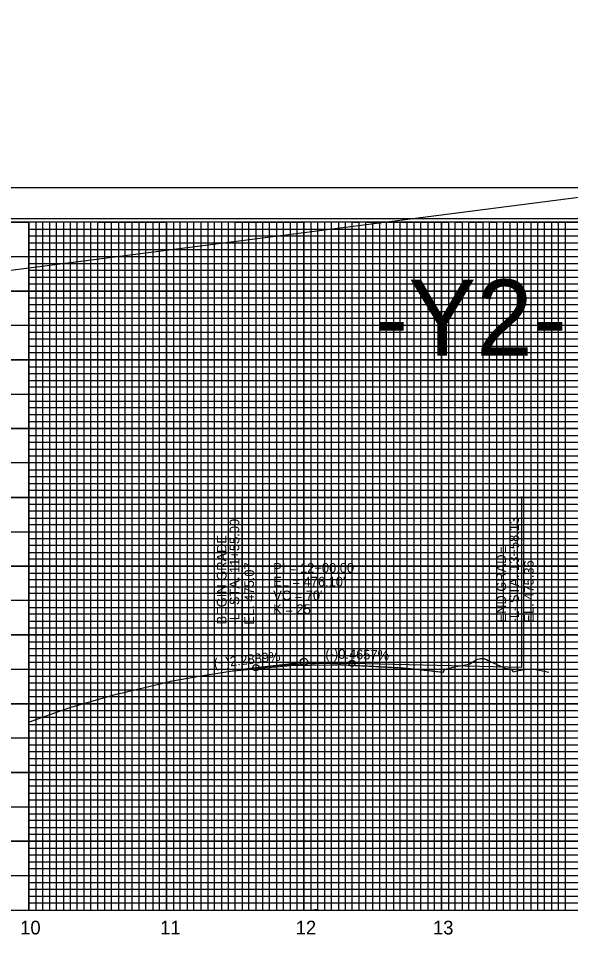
# Model space of a CAD drawing. Extents: x 571503 to 593215, y -77195 to -51828.
# Drawn here: x 586568 to 586970, y -53168 to -52498 of the extents above; entities that cross this region are included whole.
import ezdxf

# ---------------------------------------------------------------- set-up
doc = ezdxf.new("R2010")
doc.units = 0
for name, color, linetype in [('Default', 7, 'Continuous'), ('Exist Vertical Profile Ground Line', 7, 'Continuous'), ('Exist Vertical Profile Horizontal Axis Label Major', 7, 'Continuous'), ('Prop PFL Text', 7, 'Continuous'), ('Prop Vertical Profile Curve Label', 7, 'Continuous'), ('Prop Vertical Profile Grade', 7, 'Continuous'), ('Prop Vertical Profile Grade Label', 7, 'Continuous'), ('Prop VPI Label', 7, 'Continuous'), ('Sheet Clip Boundary CELL', 7, 'Continuous'), ('Sheet DOT Grid CELL', 7, 'Continuous'), ('Sheet Plot Border Inside CELL', 7, 'Continuous'), ('Sheet Plot Border Outside CELL', 7, 'Continuous'), ('Sheet Profile CELL', 7, 'Continuous'), ('Sheet Profile Grid Major CELL', 7, 'Continuous'), ('Sheet Profile Grid Middle CELL', 7, 'Continuous'), ('Sheet Profile Grid Minor CELL', 7, 'Continuous')]:
    doc.layers.add(name, color=color, linetype=linetype)

msp = doc.modelspace()

# ---------------------------------------------------------------- linework, layer by layer
at = {"layer": 'Default'}
msp.add_line((586525.93, -53146.12), (586575.93, -53146.12), dxfattribs=at)
at = {"layer": 'Exist Vertical Profile Ground Line'}
for points in [[(586878.41, -52970.95), (586878.53, -52970.95), (586879.2, -52970.94), (586879.66, -52970.83), (586880.92, -52970.53), (586882.18, -52970.22), (586883.43, -52969.9), (586884.69, -52969.58), (586885.94, -52969.26), (586887.2, -52968.93), (586887.9, -52968.74), (586888.46, -52968.66), (586889.71, -52968.48), (586890.97, -52968.29), (586892.23, -52968.1), (586893.48, -52967.9), (586894.74, -52967.7), (586895.99, -52967.5), (586896.12, -52967.48), (586897.25, -52966.75), (586898.51, -52965.94), (586899.76, -52965.11), (586901.02, -52964.28), (586901.4, -52964.02), (586902.28, -52963.83), (586903.53, -52963.54), (586904.37, -52963.34), (586904.79, -52963.31), (586906.04, -52963.2), (586906.68, -52963.14), (586907.3, -52963.43), (586908.56, -52964.03), (586909.81, -52964.62), (586911.07, -52965.21), (586912.33, -52965.8), (586913.58, -52966.38), (586921.58, -52970.06), (586926.71, -52970.98), (586928.18, -52972.84), (586932.26, -52971.92), (586937.85, -52971.04), (586942.73, -52970.78), (586953.96, -52973.11), (586954.06, -52973.13)], [(586575.93, -53009.48), (586576.18, -53009.4), (586576.18, -53009.4), (586607.14, -52998.5), (586607.29, -52998.45), (586608.38, -52998.1), (586635.32, -52990.4), (586639.22, -52989.26), (586646.02, -52987.64), (586648.78, -52987.02), (586678.39, -52979.89), (586678.74, -52979.81), (586696.99, -52976.55), (586699.56, -52976.17), (586724.04, -52972.33), (586724.63, -52972.27), (586755.51, -52969.4), (586756.19, -52969.34), (586765.89, -52968.43), (586765.91, -52968.43), (586795.49, -52967.85), (586796.19, -52967.84), (586796.75, -52967.83), (586798.01, -52967.8), (586798.12, -52967.8), (586799.26, -52967.78), (586800.52, -52967.76), (586801.77, -52967.73), (586802.47, -52967.72), (586803.03, -52967.74), (586803.71, -52967.77), (586804.29, -52967.8), (586805.54, -52967.86), (586806.8, -52967.92), (586808.06, -52967.98), (586809.31, -52968.04), (586810.57, -52968.1), (586811.82, -52968.16), (586813.08, -52968.22), (586814.34, -52968.28), (586815.59, -52968.35), (586816.85, -52968.41), (586818.11, -52968.47), (586819.36, -52968.54), (586820.62, -52968.61), (586821.87, -52968.67), (586823.13, -52968.74), (586824.39, -52968.81), (586825.64, -52968.87), (586826.9, -52968.94), (586828.16, -52969.01), (586829.41, -52969.08), (586830.39, -52969.14), (586830.67, -52969.15), (586831.92, -52969.22), (586833.18, -52969.28), (586834.44, -52969.35), (586835.69, -52969.41), (586836.95, -52969.48), (586838.21, -52969.54), (586839.46, -52969.61), (586840.7, -52969.68), (586840.72, -52969.68), (586841.97, -52969.75), (586843.23, -52969.83), (586844.49, -52969.9), (586845.74, -52969.97), (586847, -52970.05), (586848.26, -52970.12), (586849.51, -52970.2), (586850.59, -52970.27), (586850.77, -52970.29), (586852.03, -52970.42), (586853.28, -52970.56), (586854.54, -52970.7), (586855.79, -52970.83), (586857.05, -52970.97), (586858.31, -52971.11), (586859.56, -52971.25), (586860.82, -52971.39), (586862.08, -52971.53), (586863.33, -52971.67), (586864.59, -52971.81), (586864.78, -52971.83), (586865.84, -52971.95), (586867.1, -52972.08), (586868.36, -52972.22), (586869.19, -52972.31), (586869.61, -52972.36), (586870.87, -52972.51), (586872.13, -52972.66), (586872.56, -52972.71), (586873.38, -52972.78), (586874.64, -52972.88), (586875.89, -52972.99), (586876.26, -52973.02), (586877.15, -52973.07), (586877.39, -52973.08), (586877.89, -52971.77), (586878.19, -52970.94), (586878.41, -52970.95)]]:
    msp.add_lwpolyline(points, dxfattribs=at)
at = {"layer": 'Prop PFL Text'}
msp.add_line((571799.62, -54572.45), (593215.36, -51828.37), dxfattribs=at)
at = {"layer": 'Prop Vertical Profile Curve Label'}
for centre in [(586810.93, -52966.69), (586740.93, -52969.88)]:
    msp.add_circle(centre, 2.25, dxfattribs=at)
at = {"layer": 'Prop Vertical Profile Grade'}
for p, q in [((586730.93, -52971.02), (586740.93, -52969.88)), ((586810.93, -52966.69), (586934.25, -52969.56))]:
    msp.add_line(p, q, dxfattribs=at)
msp.add_spline([(586740.93, -52969.88), (586742.33, -52969.72), (586743.73, -52969.57), (586745.13, -52969.42), (586746.53, -52969.27), (586747.93, -52969.13), (586749.33, -52968.99), (586750.73, -52968.85), (586752.13, -52968.72), (586753.53, -52968.59), (586754.93, -52968.47), (586756.33, -52968.35), (586757.73, -52968.23), (586759.13, -52968.12), (586760.53, -52968.01), (586761.93, -52967.91), (586763.33, -52967.81), (586764.73, -52967.71), (586766.13, -52967.62), (586767.53, -52967.53), (586768.93, -52967.45), (586770.33, -52967.36), (586771.73, -52967.29), (586773.13, -52967.21), (586774.53, -52967.14), (586775.93, -52967.08), (586777.33, -52967.02), (586778.73, -52966.96), (586780.13, -52966.9), (586781.53, -52966.85), (586782.93, -52966.81), (586784.33, -52966.77), (586785.73, -52966.73), (586787.13, -52966.69), (586788.53, -52966.66), (586789.93, -52966.63), (586791.33, -52966.61), (586792.73, -52966.59), (586794.13, -52966.57), (586795.53, -52966.56), (586796.93, -52966.56), (586798.33, -52966.55), (586799.73, -52966.55), (586801.13, -52966.55), (586802.53, -52966.56), (586803.93, -52966.57), (586805.33, -52966.59), (586806.73, -52966.61), (586808.13, -52966.63), (586809.53, -52966.66), (586810.93, -52966.69)], degree=3, dxfattribs=at)
at = {"layer": 'Prop VPI Label'}
for p, q in [((586730.93, -52971.02), (586730.93, -52846.89)), ((586934.25, -52969.56), (586934.25, -52845.43)), ((586740.93, -52969.88), (586773.2, -52966.19)), ((586810.93, -52966.69), (586778.68, -52965.94))]:
    msp.add_line(p, q, dxfattribs=at)
msp.add_circle((586775.93, -52965.87), 2.75, dxfattribs=at)
at = {"layer": 'Sheet Clip Boundary CELL'}
msp.add_lwpolyline([(585975.93, -52646.12), (585975.93, -53146.12), (587375.93, -53146.12), (587375.93, -52783.67), (587225.88, -52783.67), (587225.88, -52646.12)], close=True, dxfattribs=at)
at = {"layer": 'Sheet DOT Grid CELL'}
for p, q in [((586575.93, -53146.12), (586575.93, -52646.12)), ((586575.93, -53146.12), (586575.93, -52646.12)), ((586625.93, -53146.12), (586625.93, -52646.12)), ((586625.93, -53146.12), (586625.93, -52646.12)), ((586675.93, -53146.12), (586675.93, -52646.12)), ((586675.93, -53146.12), (586675.93, -52646.12)), ((586725.93, -53146.12), (586725.93, -52646.12)), ((586725.93, -53146.12), (586725.93, -52646.12)), ((586775.93, -53146.12), (586775.93, -52646.12)), ((586775.93, -53146.12), (586775.93, -52646.12)), ((586825.93, -53146.12), (586825.93, -52646.12)), ((586825.93, -53146.12), (586825.93, -52646.12)), ((586875.93, -53146.12), (586875.93, -52646.12)), ((586875.93, -53146.12), (586875.93, -52646.12)), ((586925.93, -53146.12), (586925.93, -52646.12)), ((586925.93, -53146.12), (586925.93, -52646.12)), ((587225.88, -52696.12), (585925.93, -52696.12)), ((585925.93, -52746.12), (587225.88, -52746.12)), ((587225.88, -52746.12), (585925.93, -52746.12)), ((585925.93, -52796.12), (587425.93, -52796.12)), ((587425.93, -52796.12), (585925.93, -52796.12)), ((585925.93, -52846.12), (587425.93, -52846.12)), ((587425.93, -52846.12), (586575.93, -52846.12)), ((587425.93, -52896.12), (585925.93, -52896.12)), ((586575.93, -52896.12), (587425.93, -52896.12)), ((585925.93, -52946.12), (587425.93, -52946.12)), ((587425.93, -52946.12), (585925.93, -52946.12)), ((585925.93, -52996.12), (587425.93, -52996.12)), ((587425.93, -52996.12), (585925.93, -52996.12)), ((585925.93, -53046.12), (587425.93, -53046.12)), ((587425.93, -53046.12), (585925.93, -53046.12)), ((585925.93, -53096.12), (587425.93, -53096.12)), ((587425.93, -53096.12), (585925.93, -53096.12))]:
    msp.add_line(p, q, dxfattribs=at)
at = {"layer": 'Sheet Plot Border Inside CELL'}
msp.add_lwpolyline([(585771.93, -53698.67), (587438.43, -53698.67), (587438.43, -52643.57), (585771.93, -52643.57)], close=True, dxfattribs=at)
at = {"layer": 'Sheet Plot Border Outside CELL'}
msp.add_lwpolyline([(585758.93, -53721.12), (587442.93, -53721.12), (587442.93, -52621.12), (585758.93, -52621.12)], close=True, dxfattribs=at)
at = {"layer": 'Sheet Profile CELL'}
for p, q in [((587442.93, -52621.12), (585758.93, -52621.12)), ((585925.93, -53146.12), (587425.93, -53146.12))]:
    msp.add_line(p, q, dxfattribs=at)
msp.add_lwpolyline([(587425.93, -52646.12), (585925.93, -52646.12), (585925.93, -53696.12), (587425.93, -53696.12)], close=True, dxfattribs=at)
at = {"layer": 'Sheet Profile Grid Major CELL'}
for points in [[(586525.93, -52646.12), (586575.93, -52646.12), (586575.93, -53146.12), (586625.93, -53146.12), (586625.93, -52646.12), (586675.93, -52646.12), (586675.93, -53146.12), (586725.93, -53146.12), (586725.93, -52646.12), (586775.93, -52646.12), (586775.93, -53146.12), (586825.93, -53146.12), (586825.93, -52646.12), (586875.93, -52646.12), (586875.93, -53146.12), (586925.93, -53146.12), (586925.93, -52646.12), (586975.93, -52646.12)], [(585925.93, -52696.12), (587225.93, -52696.12)], [(587225.93, -52746.12), (585925.93, -52746.12), (585925.93, -52796.12), (587425.93, -52796.12)], [(587425.93, -52846.12), (585925.93, -52846.12), (585925.93, -52896.12), (587425.93, -52896.12)], [(587425.93, -52946.12), (585925.93, -52946.12), (585925.93, -52996.12), (587425.93, -52996.12)], [(587425.93, -53046.12), (585925.93, -53046.12), (585925.93, -53046.12), (585925.93, -53096.12), (587425.93, -53096.12)]]:
    msp.add_lwpolyline(points, dxfattribs=at)
at = {"layer": 'Sheet Profile Grid Middle CELL'}
for p, q in [((586600.93, -52646.12), (586600.93, -53146.12)), ((586650.93, -53146.12), (586650.93, -52646.12)), ((586700.93, -52646.12), (586700.93, -53146.12)), ((586750.93, -53146.12), (586750.93, -52646.12)), ((586800.93, -52646.12), (586800.93, -53146.12)), ((586850.93, -53146.12), (586850.93, -52646.12)), ((586900.93, -52646.12), (586900.93, -53146.12)), ((586950.93, -53146.12), (586950.93, -52646.12)), ((585925.93, -52671.12), (587225.88, -52671.12)), ((586550.93, -52896.12), (586600.93, -52896.12)), ((586650.93, -52896.12), (586700.93, -52896.12)), ((586750.93, -52896.12), (586800.93, -52896.12)), ((586850.93, -52896.12), (586900.93, -52896.12)), ((586600.93, -53146.12), (586650.93, -53146.12)), ((586700.93, -53146.12), (586750.93, -53146.12)), ((586800.93, -53146.12), (586850.93, -53146.12)), ((586900.93, -53146.12), (586950.93, -53146.12))]:
    msp.add_line(p, q, dxfattribs=at)
for points in [[(587225.93, -52721.12), (585925.93, -52721.12), (585925.93, -52771.12), (587225.93, -52771.12)], [(587425.93, -52821.12), (585925.93, -52821.12), (585925.93, -52871.12), (587250.93, -52871.12)], [(587425.93, -52921.12), (585925.93, -52921.12), (585925.93, -52971.12), (587425.93, -52971.12)], [(587425.93, -53021.12), (585925.93, -53021.12), (585925.93, -53071.12), (587425.93, -53071.12)], [(587425.93, -53121.12), (585925.93, -53121.12)]]:
    msp.add_lwpolyline(points, dxfattribs=at)
at = {"layer": 'Sheet Profile Grid Minor CELL'}
for p, q in [((586580.93, -52646.12), (586580.93, -53146.12)), ((586585.93, -53146.12), (586585.93, -52646.12)), ((586590.93, -52646.12), (586590.93, -53146.12)), ((586595.93, -53146.12), (586595.93, -52646.12)), ((586605.93, -52646.12), (586605.93, -53146.12)), ((586610.93, -53146.12), (586610.93, -52646.12)), ((586615.93, -52646.12), (586615.93, -53146.12)), ((586620.93, -53146.12), (586620.93, -52646.12)), ((586630.93, -52646.12), (586630.93, -53146.12)), ((586635.93, -53146.12), (586635.93, -52646.12)), ((586640.93, -52646.12), (586640.93, -53146.12)), ((586645.93, -53146.12), (586645.93, -52646.12)), ((586655.93, -52646.12), (586655.93, -53146.12)), ((586660.93, -53146.12), (586660.93, -52646.12)), ((586665.93, -52646.12), (586665.93, -53146.12)), ((586670.93, -53146.12), (586670.93, -52646.12)), ((586680.93, -52646.12), (586680.93, -53146.12)), ((586685.93, -53146.12), (586685.93, -52646.12)), ((586690.93, -52646.12), (586690.93, -53146.12)), ((586695.93, -53146.12), (586695.93, -52646.12)), ((586705.93, -52646.12), (586705.93, -53146.12)), ((586710.93, -53146.12), (586710.93, -52646.12)), ((586715.93, -52646.12), (586715.93, -53146.12)), ((586720.93, -53146.12), (586720.93, -52646.12)), ((586730.93, -52646.12), (586730.93, -53146.12)), ((586735.93, -53146.12), (586735.93, -52646.12)), ((586740.93, -52646.12), (586740.93, -53146.12)), ((586745.93, -53146.12), (586745.93, -52646.12)), ((586755.93, -52646.12), (586755.93, -53146.12)), ((586760.93, -53146.12), (586760.93, -52646.12)), ((586765.93, -52646.12), (586765.93, -53146.12)), ((586770.93, -53146.12), (586770.93, -52646.12)), ((586780.93, -52646.12), (586780.93, -53146.12)), ((586785.93, -53146.12), (586785.93, -52646.12)), ((586790.93, -52646.12), (586790.93, -53146.12)), ((586795.93, -53146.12), (586795.93, -52646.12)), ((586805.93, -52646.12), (586805.93, -53146.12)), ((586575.93, -52651.12), (587225.93, -52651.12)), ((587225.93, -52656.12), (586575.93, -52656.31)), ((586575.93, -52661.12), (587225.93, -52661.12)), ((587225.88, -52781.12), (586575.93, -52781.12)), ((587375.93, -52786.12), (586575.93, -52786.12)), ((587375.93, -52791.12), (586575.93, -52791.12)), ((586575.93, -52801.12), (587375.93, -52801.12)), ((587375.93, -52806.12), (586575.93, -52806.12)), ((586575.93, -52811.12), (587375.93, -52811.12)), ((587375.93, -52831.12), (586575.93, -52831.12)), ((586575.93, -52836.12), (587375.93, -52836.12)), ((587375.93, -52856.12), (586575.93, -52856.12)), ((586575.93, -52861.12), (587375.93, -52861.12)), ((587375.93, -52881.12), (586575.93, -52881.12)), ((586575.93, -52886.12), (587375.93, -52886.12)), ((587375.93, -52891.12), (586575.93, -52891.12)), ((586570.93, -52896.12), (586580.93, -52896.12)), ((586585.93, -52896.12), (586590.93, -52896.12)), ((586595.93, -52896.12), (586605.93, -52896.12)), ((586610.93, -52896.12), (586615.93, -52896.12)), ((586620.93, -52896.12), (586630.93, -52896.12)), ((586635.93, -52896.12), (586640.93, -52896.12)), ((586645.93, -52896.12), (586655.93, -52896.12)), ((586660.93, -52896.12), (586665.93, -52896.12)), ((586670.93, -52896.12), (586680.93, -52896.12)), ((586685.93, -52896.12), (586690.93, -52896.12)), ((586695.93, -52896.12), (586705.93, -52896.12)), ((586710.93, -52896.12), (586715.93, -52896.12)), ((586720.93, -52896.12), (586730.93, -52896.12)), ((586735.93, -52896.12), (586740.93, -52896.12)), ((586745.93, -52896.12), (586755.93, -52896.12)), ((586760.93, -52896.12), (586765.93, -52896.12)), ((586770.93, -52896.12), (586780.93, -52896.12)), ((586785.93, -52896.12), (586790.93, -52896.12)), ((586795.93, -52896.12), (586805.93, -52896.12)), ((586575.93, -52901.12), (587375.93, -52901.12)), ((587375.93, -52906.12), (586575.93, -52906.12)), ((586575.93, -52911.12), (587375.93, -52911.12)), ((587375.93, -52916.12), (586575.93, -52916.12)), ((586575.93, -52926.12), (587375.93, -52926.12)), ((587375.93, -52931.12), (586575.93, -52931.12)), ((586575.93, -52936.12), (587375.93, -52936.12)), ((587375.93, -52941.12), (586575.93, -52941.12)), ((586575.93, -52951.12), (587375.93, -52951.12)), ((587375.93, -52956.12), (586575.93, -52956.12)), ((586575.93, -52961.12), (587375.93, -52961.12)), ((587375.93, -52966.12), (586575.93, -52966.12)), ((586575.93, -52976.12), (587375.93, -52976.12)), ((587375.93, -52981.12), (586575.93, -52981.12)), ((586575.93, -52986.12), (587375.93, -52986.12)), ((587375.93, -52991.12), (586575.93, -52991.12)), ((586575.93, -53001.12), (587375.93, -53001.12)), ((587375.93, -53006.12), (586575.93, -53006.12)), ((586575.93, -53011.12), (587375.93, -53011.12)), ((587375.93, -53016.12), (586575.93, -53016.12)), ((586575.93, -53026.12), (587375.93, -53026.12)), ((587375.93, -53031.12), (586575.93, -53031.12)), ((587375.93, -53036.12), (586575.93, -53036.12)), ((587375.93, -53041.12), (586575.93, -53041.12)), ((586575.93, -53051.12), (587375.93, -53051.12)), ((587375.93, -53056.12), (586575.93, -53056.12)), ((586575.93, -53061.12), (587375.93, -53061.12)), ((587375.93, -53066.12), (586575.93, -53066.12)), ((586575.93, -53076.12), (587375.93, -53076.12)), ((587375.93, -53081.12), (586575.93, -53081.12)), ((586575.93, -53086.12), (587375.93, -53086.12)), ((587375.93, -53091.12), (586575.93, -53091.12)), ((586575.93, -53101.12), (587375.93, -53101.12)), ((587375.93, -53106.12), (586575.93, -53106.12)), ((586575.93, -53111.12), (587375.93, -53111.12)), ((587375.93, -53116.12), (586575.93, -53116.12)), ((586575.93, -53126.12), (587375.93, -53126.12)), ((587375.93, -53131.12), (586575.93, -53131.12)), ((586575.93, -53136.12), (587375.93, -53136.12)), ((586565.93, -53146.12), (586570.93, -53146.12)), ((586580.93, -53146.12), (586585.93, -53146.12)), ((586590.93, -53146.12), (586595.93, -53146.12)), ((586605.93, -53146.12), (586610.93, -53146.12)), ((586615.93, -53146.12), (586620.93, -53146.12)), ((586630.93, -53146.12), (586630.93, -53146.12)), ((586630.93, -53146.12), (586635.93, -53146.12)), ((586640.93, -53146.12), (586645.93, -53146.12)), ((586655.93, -53146.12), (586660.93, -53146.12)), ((586665.93, -53146.12), (586670.93, -53146.12)), ((586680.93, -53146.12), (586685.93, -53146.12)), ((586690.93, -53146.12), (586695.93, -53146.12)), ((586705.93, -53146.12), (586710.93, -53146.12)), ((586715.93, -53146.12), (586720.93, -53146.12)), ((586730.93, -53146.12), (586735.93, -53146.12)), ((586740.93, -53146.12), (586745.93, -53146.12)), ((586755.93, -53146.12), (586760.93, -53146.12)), ((586765.93, -53146.12), (586770.93, -53146.12)), ((586780.93, -53146.12), (586785.63, -53145.57)), ((586785.63, -53145.57), (586785.93, -53146.12)), ((586790.93, -53146.12), (586795.93, -53146.12)), ((586805.93, -53146.12), (586810.93, -53146.12))]:
    msp.add_line(p, q, dxfattribs=at)
for points in [[(586810.93, -53146.12), (586810.93, -52646.12), (586815.93, -52646.12), (586815.93, -53146.12), (586820.93, -53146.12), (586820.93, -52646.12), (586830.93, -52646.12), (586830.93, -53146.12), (586835.93, -53146.12), (586835.93, -52646.12), (586840.93, -52646.12), (586840.93, -53146.12), (586845.93, -53146.12), (586845.93, -52646.12), (586855.93, -52646.12), (586855.93, -53146.12), (586860.93, -53146.12), (586860.93, -52646.12), (586865.93, -52646.12), (586865.93, -53146.12), (586870.93, -53146.12), (586870.93, -52646.12), (586880.93, -52646.12), (586880.93, -53146.12), (586885.93, -53146.12), (586885.93, -52646.12), (586890.93, -52646.12), (586890.93, -53146.12), (586895.93, -53146.12), (586895.93, -52646.12), (586905.93, -52646.12), (586905.93, -53146.12), (586910.93, -53146.12), (586910.93, -52646.12), (586915.93, -52646.12), (586915.93, -53146.12), (586920.93, -53146.12), (586920.93, -52646.12), (586930.93, -52646.12), (586930.93, -53146.12), (586935.93, -53146.12), (586935.93, -52646.12), (586940.93, -52646.12), (586940.93, -53146.12), (586945.93, -53146.12), (586945.93, -52646.12), (586955.93, -52646.12), (586955.93, -53146.12), (586960.93, -53146.12), (586960.93, -52646.12), (586965.93, -52646.12), (586965.93, -53146.12), (586970.93, -53146.12)], [(587225.93, -52666.12), (586575.93, -52666.12)], [(586575.93, -52676.12), (587225.93, -52676.12)], [(587225.88, -52681.12), (586575.93, -52681.12)], [(586575.93, -52686.12), (587225.93, -52686.12)], [(587225.93, -52691.12), (586575.93, -52691.12)], [(586575.93, -52701.12), (587225.93, -52701.12)], [(587225.93, -52706.12), (586575.93, -52706.12)], [(586575.93, -52711.12), (587225.93, -52711.12)], [(587225.93, -52716.12), (586575.93, -52716.12)], [(586575.93, -52726.12), (587225.93, -52726.12)], [(587225.93, -52731.12), (586575.93, -52731.12)], [(586575.93, -52736.12), (587225.93, -52736.12)], [(587225.93, -52741.12), (586575.93, -52741.12)], [(586575.93, -52751.12), (587225.93, -52751.12)], [(587225.93, -52756.22), (586575.93, -52756.22)], [(586575.93, -52761.12), (587225.93, -52761.12)], [(587225.93, -52766.12), (586575.93, -52766.12)], [(586575.93, -52776.12), (587225.93, -52776.12)], [(587375.93, -52816.12), (586575.93, -52816.12)], [(586575.93, -52826.12), (587375.93, -52826.12)], [(587375.93, -52841.12), (586575.93, -52841.12)], [(586575.93, -52851.12), (587375.93, -52851.12)], [(587375.93, -52866.12), (586575.93, -52866.12)], [(586575.93, -52876.12), (587375.93, -52876.12)], [(587375.93, -53141.12), (586575.93, -53141.12)]]:
    msp.add_lwpolyline(points, dxfattribs=at)

# ---------------------------------------------------------------- texts
at = {"layer": 'Default'}
msp.add_text('-Y2-', height=55.361, dxfattribs=at).set_placement((586827.16, -52743.19))
at = {"layer": 'Exist Vertical Profile Horizontal Axis Label Major'}
for s, p in [('10', (586569.52, -53163.87)), ('11', (586671.36, -53163.87)), ('12', (586769.9, -53163.87)), ('13', (586869.74, -53163.87))]:
    msp.add_text(s, height=10, dxfattribs=at).set_placement(p)
at = {"layer": 'Prop Vertical Profile Curve Label'}
for s, p in [("VC = 70'", (586753.55, -52920.87)), ('K = 25', (586753.55, -52930.84))]:
    msp.add_text(s, height=7, dxfattribs=at).set_placement(p)
at = {"layer": 'Prop Vertical Profile Grade Label'}
for s, rotation, p in [('(+)2.2889%', 6.52878, (586710.72, -52970.32)), ('(-)0.4657%', 358.6661, (586791.42, -52963.23))]:
    msp.add_text(s, height=7, rotation=rotation, dxfattribs=at).set_placement(p)
at = {"layer": 'Prop VPI Label'}
for s, p in [('-L- STA. 11+55.00', (586728.87, -52938.5)), ('-L- STA. 13+58.13', (586932.19, -52937.04)), ('BEGIN GRADE', (586719.57, -52938.5)), ('END GRADE', (586922.89, -52937.04)), ('EL. 475.07', (586739.6, -52938.63)), ('EL. 475.36', (586942.92, -52937.17))]:
    msp.add_text(s, height=7, rotation=90, dxfattribs=at).set_placement(p)
for s, p in [('PI = 12+00.00', (586753.55, -52900.87)), ("EL = 476.10'", (586753.55, -52910.87))]:
    msp.add_text(s, height=7, dxfattribs=at).set_placement(p)

doc.saveas('drawing.dxf')
